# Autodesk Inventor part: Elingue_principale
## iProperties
Shininess: 64.0
Length Units: 11269
Angle Units: 11279
Time Units: 11290
Mass Units: 11283
Length Display Precision: 3
Angle Display Precision: 2
Compacted: True
Part Number: Elingue_principale
Document SubType Name: Modeling
Created: 2008-04
Material: Par défaut
Designer: Pascal
Density: 0.0
Volumn: 0.0
Area: 0.0
PropertySet Name: Model Information
Control State: 0
Master: False
Checked Out: False
DESIGNATION: pièce
Author: Pascal
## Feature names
1. Balayage1
2. Extrusion1
3. Extrusion2
4. Extrusion3
5. Congé1 [Fillet]
6. Congé2 [Fillet]
